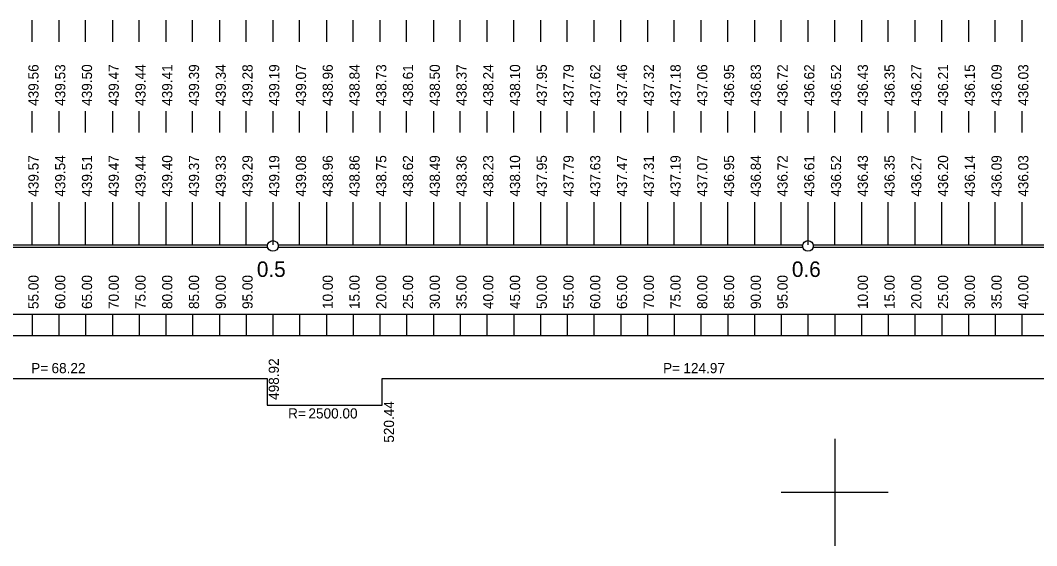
# Model space of a CAD drawing. Extents: x -240 to 1040, y 276 to 593.
# Drawn here: x 457.8 to 647.7, y 275.7 to 374 of the extents above; entities that cross this region are included whole.
import ezdxf

# ---------------------------------------------------------------- set-up
doc = ezdxf.new("R2010")
doc.units = 0
for name, color, linetype in [('1', 7, 'Continuous'), ('2', 7, 'Continuous'), ('FORMATY', 7, 'Continuous')]:
    doc.layers.add(name, color=color, linetype=linetype)

msp = doc.modelspace()

# ---------------------------------------------------------------- linework, layer by layer
at = {"layer": '1'}
for p, q in [((460, 370), (460, 374)), ((465, 374), (465, 370)), ((470, 370), (470, 374)), ((475, 374), (475, 370)), ((480, 370), (480, 374)), ((485, 374), (485, 370)), ((490, 370), (490, 374)), ((495, 374), (495, 370)), ((500, 370), (500, 374)), ((505, 374), (505, 370)), ((510, 370), (510, 374)), ((515, 374), (515, 370)), ((520, 370), (520, 374)), ((525, 374), (525, 370)), ((530, 370), (530, 374)), ((535, 374), (535, 370)), ((540, 370), (540, 374)), ((545, 374), (545, 370)), ((550, 370), (550, 374)), ((555, 374), (555, 370)), ((560, 370), (560, 374)), ((565, 374), (565, 370)), ((570, 370), (570, 374)), ((575, 374), (575, 370)), ((580, 370), (580, 374)), ((585, 374), (585, 370)), ((590, 370), (590, 374)), ((595, 374), (595, 370)), ((600, 370), (600, 374)), ((605, 374), (605, 370)), ((610, 370), (610, 374)), ((615, 374), (615, 370)), ((620, 370), (620, 374)), ((625, 374), (625, 370)), ((630, 370), (630, 374)), ((635, 374), (635, 370)), ((640, 370), (640, 374)), ((645, 374), (645, 370)), ((460, 353), (460, 357)), ((465, 357), (465, 353)), ((470, 353), (470, 357)), ((475, 357), (475, 353)), ((480, 353), (480, 357)), ((485, 357), (485, 353)), ((490, 353), (490, 357)), ((495, 357), (495, 353)), ((500, 353), (500, 357)), ((505, 357), (505, 353)), ((510, 353), (510, 357)), ((515, 357), (515, 353)), ((520, 353), (520, 357)), ((525, 357), (525, 353)), ((530, 353), (530, 357)), ((535, 357), (535, 353)), ((540, 353), (540, 357)), ((545, 357), (545, 353)), ((550, 353), (550, 357)), ((555, 357), (555, 353)), ((560, 353), (560, 357)), ((565, 357), (565, 353)), ((570, 353), (570, 357)), ((575, 357), (575, 353)), ((580, 353), (580, 357)), ((585, 357), (585, 353)), ((590, 353), (590, 357)), ((595, 357), (595, 353)), ((600, 353), (600, 357)), ((605, 357), (605, 353)), ((610, 353), (610, 357)), ((615, 357), (615, 353)), ((620, 353), (620, 357)), ((625, 357), (625, 353)), ((630, 353), (630, 357)), ((635, 357), (635, 353)), ((640, 353), (640, 357)), ((645, 357), (645, 353)), ((460, 332), (460, 340)), ((465, 340), (465, 332)), ((470, 332), (470, 340)), ((475, 340), (475, 332)), ((480, 332), (480, 340)), ((485, 340), (485, 332)), ((490, 332), (490, 340)), ((495, 340), (495, 332)), ((500, 332), (500, 340)), ((505, 340), (505, 332)), ((510, 332), (510, 340)), ((515, 340), (515, 332)), ((520, 332), (520, 340)), ((525, 340), (525, 332)), ((530, 332), (530, 340)), ((535, 340), (535, 332)), ((540, 332), (540, 340)), ((545, 340), (545, 332)), ((550, 332), (550, 340)), ((555, 340), (555, 332)), ((560, 332), (560, 340)), ((565, 340), (565, 332)), ((570, 332), (570, 340)), ((575, 340), (575, 332)), ((580, 332), (580, 340)), ((585, 340), (585, 332)), ((590, 332), (590, 340)), ((595, 340), (595, 332)), ((600, 332), (600, 340)), ((605, 340), (605, 332)), ((610, 332), (610, 340)), ((615, 340), (615, 332)), ((620, 332), (620, 340)), ((625, 340), (625, 332)), ((630, 332), (630, 340)), ((635, 340), (635, 332)), ((640, 332), (640, 340)), ((645, 340), (645, 332)), ((406, 332), (504, 332)), ((406, 331.6), (504, 331.6)), ((506, 332), (604, 332)), ((506, 331.6), (604, 331.6)), ((606, 332), (704, 332)), ((606, 331.6), (704, 331.6)), ((804.78, 319), (5, 319)), ((460, 319), (460, 315)), ((465, 319), (465, 315)), ((470, 319), (470, 315)), ((475, 319), (475, 315)), ((480, 319), (480, 315)), ((485, 319), (485, 315)), ((490, 319), (490, 315)), ((495, 319), (495, 315)), ((500, 319), (500, 315)), ((505, 319), (505, 315)), ((510, 319), (510, 315)), ((515, 319), (515, 315)), ((520, 319), (520, 315)), ((525, 319), (525, 315)), ((530, 319), (530, 315)), ((535, 319), (535, 315)), ((540, 319), (540, 315)), ((545, 319), (545, 315)), ((550, 319), (550, 315)), ((555, 319), (555, 315)), ((560, 319), (560, 315)), ((565, 319), (565, 315)), ((570, 319), (570, 315)), ((575, 319), (575, 315)), ((580, 319), (580, 315)), ((585, 319), (585, 315)), ((590, 319), (590, 315)), ((595, 319), (595, 315)), ((600, 319), (600, 315)), ((605, 319), (605, 315)), ((610, 319), (610, 315)), ((615, 319), (615, 315)), ((620, 319), (620, 315)), ((625, 319), (625, 315)), ((630, 319), (630, 315)), ((635, 319), (635, 315)), ((640, 319), (640, 315)), ((645, 319), (645, 315)), ((804.78, 315), (5, 315))]:
    msp.add_line(p, q, dxfattribs=at)
for centre in [(505, 331.8), (605, 331.8)]:
    msp.add_circle(centre, 1, dxfattribs=at)
at = {"layer": '2'}
for p, q in [((435.71, 307), (503.92, 307)), ((503.92, 307), (503.92, 302)), ((525.44, 302), (525.44, 307)), ((525.44, 307), (650.41, 307)), ((503.92, 302), (525.44, 302))]:
    msp.add_line(p, q, dxfattribs=at)
at = {"layer": 'FORMATY'}
for p, q in [((610.02, 295.74), (610.02, 275.74)), ((610.02, 295.74), (610.02, 275.74)), ((610.02, 295.74), (610.02, 275.74)), ((610.02, 295.74), (610.02, 275.74)), ((610.02, 295.74), (610.02, 275.74)), ((610.02, 295.74), (610.02, 275.74)), ((610.02, 295.74), (610.02, 275.74)), ((610.02, 295.74), (610.02, 275.74)), ((610.02, 295.74), (610.02, 275.74)), ((600.02, 285.74), (620.02, 285.74)), ((600.02, 285.74), (620.02, 285.74)), ((600.02, 285.74), (620.02, 285.74)), ((600.02, 285.74), (620.02, 285.74)), ((600.02, 285.74), (620.02, 285.74)), ((600.02, 285.74), (620.02, 285.74)), ((600.02, 285.74), (620.02, 285.74)), ((600.02, 285.74), (620.02, 285.74)), ((600.02, 285.74), (620.02, 285.74))]:
    msp.add_line(p, q, dxfattribs=at)

# ---------------------------------------------------------------- texts
at = {"layer": '1'}
for s, p in [('439.57', (461.2, 341)), ('439.54', (466.2, 341)), ('439.51', (471.2, 341)), ('439.47', (476.2, 341)), ('439.44', (481.2, 341)), ('439.40', (486.2, 341)), ('439.37', (491.2, 341)), ('439.33', (496.2, 341)), ('439.29', (501.2, 341)), ('439.19', (506.2, 341)), ('439.08', (511.2, 341)), ('438.96', (516.2, 341)), ('438.86', (521.2, 341)), ('438.75', (526.2, 341)), ('438.62', (531.2, 341)), ('438.49', (536.2, 341)), ('438.36', (541.2, 341)), ('438.23', (546.2, 341)), ('438.10', (551.2, 341)), ('437.95', (556.2, 341)), ('437.79', (561.2, 341)), ('437.63', (566.2, 341)), ('437.47', (571.2, 341)), ('437.31', (576.2, 341)), ('437.19', (581.2, 341)), ('437.07', (586.2, 341)), ('436.95', (591.2, 341)), ('436.84', (596.2, 341)), ('436.72', (601.2, 341)), ('436.61', (606.2, 341)), ('436.52', (611.2, 341)), ('436.43', (616.2, 341)), ('436.35', (621.2, 341)), ('436.27', (626.2, 341)), ('436.20', (631.2, 341)), ('436.14', (636.2, 341)), ('436.09', (641.2, 341)), ('436.03', (646.2, 341)), ('55.00', (461.2, 320)), ('60.00', (466.2, 320)), ('65.00', (471.2, 320)), ('70.00', (476.2, 320)), ('75.00', (481.2, 320)), ('80.00', (486.2, 320)), ('85.00', (491.2, 320)), ('90.00', (496.2, 320)), ('95.00', (501.2, 320)), ('10.00', (516.2, 320)), ('15.00', (521.2, 320)), ('20.00', (526.2, 320)), ('25.00', (531.2, 320)), ('30.00', (536.2, 320)), ('35.00', (541.2, 320)), ('40.00', (546.2, 320)), ('45.00', (551.2, 320)), ('50.00', (556.2, 320)), ('55.00', (561.2, 320)), ('60.00', (566.2, 320)), ('65.00', (571.2, 320)), ('70.00', (576.2, 320)), ('75.00', (581.2, 320)), ('80.00', (586.2, 320)), ('85.00', (591.2, 320)), ('90.00', (596.2, 320)), ('95.00', (601.2, 320)), ('10.00', (616.2, 320)), ('15.00', (621.2, 320)), ('20.00', (626.2, 320)), ('25.00', (631.2, 320)), ('30.00', (636.2, 320)), ('35.00', (641.2, 320)), ('40.00', (646.2, 320))]:
    msp.add_text(s, height=1.9, rotation=90, dxfattribs=at).set_placement(p)
for s, p in [('0.5', (502, 326)), ('0.6', (602, 326))]:
    msp.add_text(s, height=2.9, dxfattribs=at).set_placement(p)
at = {"layer": '2'}
for s, p in [('439.56', (461.2, 358)), ('439.53', (466.2, 358)), ('439.50', (471.2, 358)), ('439.47', (476.2, 358)), ('439.44', (481.2, 358)), ('439.41', (486.2, 358)), ('439.39', (491.2, 358)), ('439.34', (496.2, 358)), ('439.28', (501.2, 358)), ('439.19', (506.2, 358)), ('439.07', (511.2, 358)), ('438.96', (516.2, 358)), ('438.84', (521.2, 358)), ('438.73', (526.2, 358)), ('438.61', (531.2, 358)), ('438.50', (536.2, 358)), ('438.37', (541.2, 358)), ('438.24', (546.2, 358)), ('438.10', (551.2, 358)), ('437.95', (556.2, 358)), ('437.79', (561.2, 358)), ('437.62', (566.2, 358)), ('437.46', (571.2, 358)), ('437.32', (576.2, 358)), ('437.18', (581.2, 358)), ('437.06', (586.2, 358)), ('436.95', (591.2, 358)), ('436.83', (596.2, 358)), ('436.72', (601.2, 358)), ('436.62', (606.2, 358)), ('436.52', (611.2, 358)), ('436.43', (616.2, 358)), ('436.35', (621.2, 358)), ('436.27', (626.2, 358)), ('436.21', (631.2, 358)), ('436.15', (636.2, 358)), ('436.09', (641.2, 358)), ('436.03', (646.2, 358)), ('498.92', (506.12, 303)), ('520.44', (527.64, 295))]:
    msp.add_text(s, height=1.9, rotation=90, dxfattribs=at).set_placement(p)
for s, p in [('P=', (459.82, 308)), ('68.22', (463.62, 308)), ('P=', (577.92, 308)), ('124.97', (581.72, 308)), ('R=', (507.84, 299.53)), ('2500.00', (511.64, 299.53))]:
    msp.add_text(s, height=1.9, dxfattribs=at).set_placement(p)

doc.saveas('drawing.dxf')
